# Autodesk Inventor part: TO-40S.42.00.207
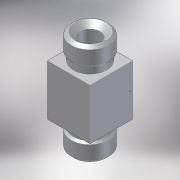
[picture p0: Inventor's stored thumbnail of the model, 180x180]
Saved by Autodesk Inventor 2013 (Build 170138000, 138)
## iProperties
Shininess: 64.0
Angle Display Precision: 2
Document Length Units: 11269
Document Angle Units: 11279
Document Time Units: 11290
Document Mass Units: 11283
Document Length Units Precision: 3
Document Angle Units Precision: 2
Created: 2002-02
Part Number: TO-40S.42.00.207
Document SubType Name: Modeling
Designer: TEvgeniy
Density: 1 g/cm^3
Material: Generic
Mass: 20.5519 g
Surface Area: 84.0708 cm^2
Volume: 20.5519 cm^3
Density: 0.0
Volumn: 0.0
Area: 0.0
PropertySet Name: Model Information
Control State: 0
Master: False
Checked Out: False
Checked Out Date: 2008-10-15
Last Check In Date: 2008-10-15
Author: TEvgeniy
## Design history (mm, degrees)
node "WorkPlane1"
sketch "Sketch1"
  geometry: L1 (182.778, 133.836)-(157.778, 133.836); L2 (182.778, 108.836)-(182.778, 133.836); L3 (157.778, 108.836)-(182.778, 108.836); L4 (157.778, 133.836)-(157.778, 108.836)
  constraints: 8 end point, 2 horizontal, 2 vertical, 1 other
  dimensions: "d1" = 25 distance of L1.start L1.end; "d3" = 25 distance of L2.start L1.start
extrude "ExtrusionBlind1" new body sketch "Sketch1" distance "d4" = 60; taper "d5" = 0 deg
node "WorkAxis1"
node "WorkPlane2"
revolve "RevolutionAngle1" stored, may be unused: angle "d27" = 360 deg
revolve "RevolutionAngle2" stored, may be unused: angle "d37" = 360 deg
revolve "RevolutionAngle3" stored, may be unused: angle "d47" = 360 deg
revolve "RevolutionAngle4" stored, may be unused: angle "d52" = 360 deg
revolve "RevolutionAngle5" stored, may be unused: angle "d62" = 360 deg
body "Solid1"
sketch "Sketch2"
  geometry: L1 (182.778, 133.836)-(182.778, 108.836) reference; L2 (182.778, 108.836)-(157.778, 108.836) reference; 1 further point
  dimensions: "d8" = 12.5 distance from line of L1 point (170.278, 121.336); "d10" = 12.5 distance from line of L2 point (170.278, 121.336)
hole "Hole1" sketch "Sketch2" diameter "d11" = 12; stored, may be unused: countersink angle "d15" = 82 deg, drill point angle "d17" = 118 deg; dims "d12" = 6, "d13" = 4, "d14" = 2, "d16" = 8
chamfer "Chamfer1" distance "d38" = 1.6; stored, may be unused: angle "d39" = 45 deg, second distance "d63" = 1.6
chamfer "Chamfer2" distance "d40" = 1.6; stored, may be unused: angle "d41" = 45 deg, second distance "d64" = 1.6
workplane "Work Plane3"
sketch "Sketch3"
  geometry: L1 (19.9, 9.642)-(19.9, 24.642); L2 (11, 9.642)-(19.9, 9.642); L3 (11, 19.542)-(11, 9.642); L4 (9.9, 20.642)-(11, 19.542); L5 (9.9, 24.642)-(9.9, 20.642); L6 (19.9, 24.642)-(9.9, 24.642); L7 (6, 9.642)-(-6, 9.642) reference; L8 (0, 4.821)-(0, 74.463)
  constraints: 14 end point, 3 vertical, 2 horizontal
  dimensions: "d20" = 15 distance of L1.start L1.end; "d22" = 4 distance of L5.start L4.start; "d24" = 45 deg angle of L4 L3; "d26" = 10 distance of L1.end L5.start
sketch "Sketch4"
  geometry: L1 (19.9, 69.642)-(19.9, 54.642); L2 (11, 69.642)-(19.9, 69.642); L3 (11, 59.742)-(11, 69.642); L4 (9.9, 58.642)-(11, 59.742); L5 (9.9, 54.642)-(9.9, 58.642); L6 (19.9, 54.642)-(9.9, 54.642); L7 (0, 4.821)-(0, 74.463); 1 further point
  constraints: 14 end point, 3 vertical, 2 horizontal
  dimensions: "d29" = 15 distance of L1.start L1.end; "d31" = 10 distance of L1.end L5.start; "d33" = 4 distance of L5.start L4.start; "d35" = 45 deg angle of L3 L4
sketch "Sketch5"
  geometry: L1 (0, 60.642)-(9, 69.642); L2 (0, 69.642)-(0, 60.642); L3 (9, 69.642)-(0, 69.642); L4 (-9.4, 69.642)-(9.4, 69.642) reference; L5 (0, 4.821)-(0, 74.463)
  constraints: 8 end point, 1 horizontal, 1 vertical
  dimensions: "d43" = 9 distance of L1.end L2.start; "d45" = 45 deg angle of L3 L1
sketch "Sketch6"
  geometry: L1 (0, 18.642)-(9, 9.642); L2 (0, 9.642)-(0, 18.642); L3 (9, 9.642)-(0, 9.642); L4 (9.4, 9.642)-(-9.4, 9.642) reference; L5 (0, 4.821)-(0, 74.463)
  constraints: 8 end point, 1 horizontal, 1 vertical
  dimensions: "d49" = 9 distance of L1.end L2.start; "d51" = 9 distance of L2.start L1.start
sketch "Sketch7"
  geometry: L1 (0, 39.642)-(12.5, 39.642); L2 (0, 33.642)-(0, 39.642); L3 (10.5, 33.642)-(0, 33.642); L4 (10.5, 27.142)-(10.5, 33.642); L5 (12.5, 27.142)-(10.5, 27.142); L6 (12.5, 39.642)-(12.5, 27.142); L7 (-9, 69.642)-(9, 69.642) reference; L8 (0, 39.642)-(12.5, 39.642); 1 further point
  constraints: 14 end point, 3 horizontal, 3 vertical
  dimensions: "d54" = 12.5 distance of L1.end L5.start; "d56" = 6 distance of L2.start L1.start; "d59" = 2 distance of L5.start L4.start; "d61" = 12.5 distance of L1.start L1.end
other parameters: "d0" = 25 (derived), "d2" = 25 (derived), "d6" = 0, "d7" = 12.5 (derived), "d9" = 12.5 (derived), "d18" = 0, "d19" = 15 (derived), "d21" = 4 (derived), "d23" = 45 deg (derived), "d28" = 15 (derived), "d32" = 4 (derived), "d34" = 45 deg (derived), "d36" = 0 (derived), "d42" = 9 (derived), "d44" = 45 deg (derived), "d46" = 0 (derived), "d48" = 9 (derived), "d50" = 9 (derived), "d53" = 12.5 (derived), "d55" = 6 (derived), "d57" = 0 (derived), "d58" = 2 (derived), "d60" = 12.5 (derived)
